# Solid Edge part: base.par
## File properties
Title: Base
Author: Robert a Rhodes jr
Template: Normal.par
Last saved by: TIET
Revision: 22
Application: Solid Edge
Accuracy: 0.99
Material: aluminum
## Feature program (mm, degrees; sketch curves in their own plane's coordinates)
sketch for "unnamed Protrusion 1" plane through (0, 0, 0) normal (0, 0, 1) x-axis (1, 0, 0)
  line (-85, 25) -> (-85, -25)
  arc centre (-80, -25) radius 5 from (-85, -25) to (-80, -30) ccw
  line (-80, -30) -> (80, -30)
  arc centre (80, -25) radius 5 from (85, -25) to (80, -30) cw
  line (85, -25) -> (85, 25)
  arc centre (80, 25) radius 5 from (80, 30) to (85, 25) cw
  line (80, 30) -> (-80, 30)
  arc centre (-80, 25) radius 5 from (-85, 25) to (-80, 30) cw
extrude "unnamed Protrusion 1" add finite 20 along +normal
sketch for "ExtrudedProtrusion_2" plane through (5, -12, 10) normal (0, -1, 0) x-axis (1, 0, 0)
  line (-50, 10) -> (-50, 50)
  arc centre (15, 50) radius 65 from (-50, 50) to (-20, 104.7723) cw
  line (-20, 104.7723) -> (-20, 144)
  arc centre (-17, 144) radius 3 from (-20, 144) to (-17, 147) cw
  line (-17, 147) -> (37, 147)
  arc centre (37, 144) radius 3 from (37, 147) to (40, 144) cw
  line (40, 144) -> (40, 75)
  line (40, 75) -> (-12, 75)
  line (-12, 28.959) -> (-12, 75)
  line (10, 10) -> (-12, 28.959)
  line (28, 35) -> (10, 10)
  line (40, 35) -> (28, 35)
  line (40, 35) -> (40, 10)
extrude "ExtrudedProtrusion_2" add  Plane_Distance = 18 mm
sketch for "unnamed Cutout 1" plane through (5, -12, 88.5) normal (0, -1, 0) x-axis (1, 0, 0)
  line (-20, -68.5) -> (-20, 4.7281)
  arc centre (-25, 4.7281) radius 5 from (-28.8, 7.9777) to (-20, 4.7281) cw
  arc centre (13, -27.7681) radius 55 from (-42, -27.7681) to (-28.8, 7.9777) cw
  line (-42, -68.5) -> (-42, -27.7681)
  line (-42, -68.5) -> (-20, -68.5)
extrude "unnamed Cutout 1" cut finite 10 along -normal
sketch for "ExtrudedCutout_2" plane through (5, 0, 0) normal (0, 0, -1) x-axis (1, 0, 0)
  line (-10, 1) -> (-10, -19)
  line (-10, -19) -> (30, -19)
  line (30, -19) -> (30, 1)
  line (30, 1) -> (-10, 1)
  dimension (linear) = 10
extrude "ExtrudedCutout_2" cut finite 147 along -normal
sketch for "ExtrudedProtrusion_3" plane through (25, 9, 157) normal (0, 0, 1) x-axis (1, 0, 0)
  circle centre (-10, 0) radius 15
  dimension (linear) = 10
extrude "ExtrudedProtrusion_3" add finite 18 along +normal
sketch for "Hole_1" plane through (25, 9, 175) normal (0, 0, 1) x-axis (1, 0, 0)
  hole centre (-10, 0) bore radius 10
hole "Hole_1" diameter 20 finite
sketch for "Hole_2" plane through (45, 9, 119.9119) normal (1, 0, 0) x-axis (0, 1, 0)
  hole centre (1, 20.0881) bore radius 4
  dimension (linear) = 1
hole "Hole_2" diameter 8 through
mirror "unnamed Mirror 1" of "unnamed Cutout 1" about plane through (5, 9, 88.7059) normal (0, -1, 0)
extrude "unnamed Cutout 2" cut finite 10
fillet "Round_1" radius 3
sketch for "Hole_3" plane through (0, 0, 20) normal (0, 0, 1) x-axis (1, 0, 0)
  hole centre (70, 0) bore radius 6.5
hole "Hole_3" diameter 13 through
sketch for "unnamed Hole 1" plane through (0, 0, 20) normal (0, 0, 1) x-axis (1, 0, 0)
  hole centre (-70, 0) bore radius 6.5
  dimension (linear) = 70
  dimension (linear) = 70
hole "unnamed Hole 1" through
pattern "unnamed Pattern 1" of "Hole_3", "unnamed Hole 1"
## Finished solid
Body 1: solid body, 61 faces, 164 edges, 100 vertices.
  Faces by surface: plane 37, cylinder 23, torus 1
  Edges by curve: line 114, circle 50
Bounding box of the edges (mm; curved faces can reach further): 170.000 x 60.000 x 175.000, from (-85, -30, 0) to (85, 30, 175).
Cylindrical faces by radius (mm): R3 x8, R4 x2, R5 x6, R6.5 x2, R10 x1, R15 x1, R55 x2, R65 x1
Toroidal faces (ring radius, tube radius in mm): R18 r3 x1
Planar faces by outward normal: +x 8, +y 4, +z 5, -x 7, -y 6, -z 4, oblique 3
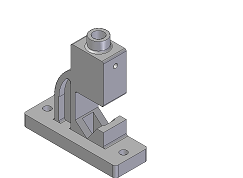
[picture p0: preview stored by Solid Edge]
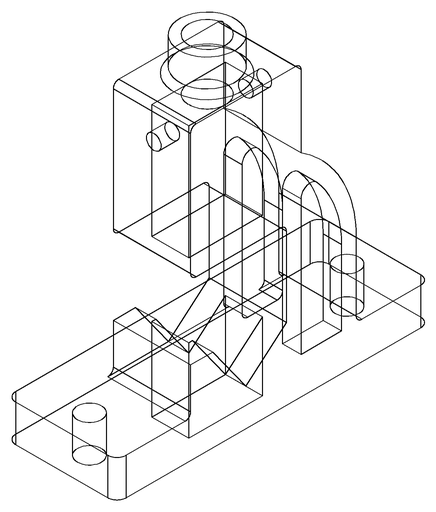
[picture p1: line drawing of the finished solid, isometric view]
